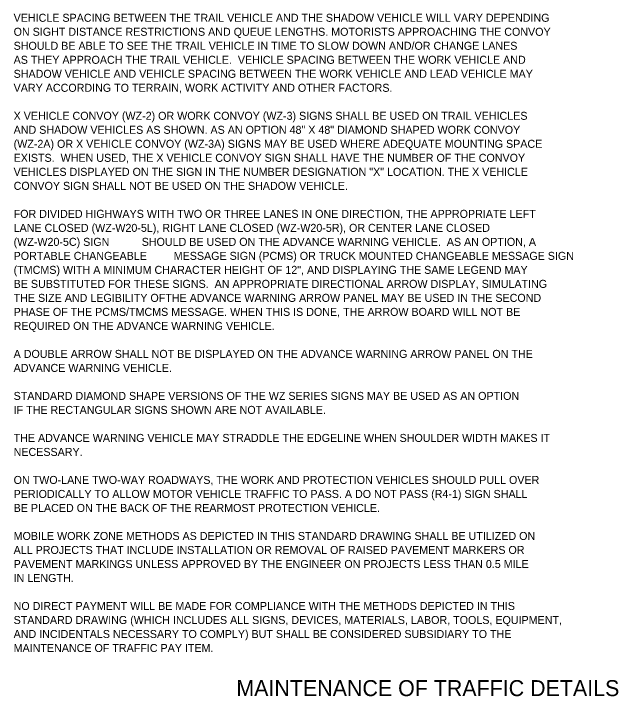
# Model space of a CAD drawing. Extents: x -747 to 834, y -5485 to -3577.
# Drawn here: x 360 to 813, y -5480 to -4968 of the extents above; entities that cross this region are included whole.
import ezdxf

# ---------------------------------------------------------------- set-up
doc = ezdxf.new("R2010")
doc.units = 0
doc.layers.add('R_Annotation', color=7, linetype='Continuous')
doc.layers.add('Working Level 1', color=7, linetype='Continuous')

msp = doc.modelspace()

# ---------------------------------------------------------------- texts
at = {"layer": 'R_Annotation'}
msp.add_text('MAINTENANCE OF TRAFFIC DETAILS', height=12, dxfattribs=at).set_placement((526.6, -5479.51))
at = {"layer": 'Working Level 1'}
for s, p in [('VEHICLE SPACING BETWEEN THE TRAIL VEHICLE AND THE SHADOW VEHICLE WILL VARY DEPENDING ', (359.65, -4973.93)), ('ON SIGHT DISTANCE RESTRICTIONS AND QUEUE LENGTHS. MOTORISTS APPROACHING THE CONVOY ', (359.65, -4984.43)), ('SHOULD BE ABLE TO SEE THE TRAIL VEHICLE IN TIME TO SLOW DOWN AND/OR CHANGE LANES ', (359.65, -4994.93)), ('AS THEY APPROACH THE TRAIL VEHICLE.  VEHICLE SPACING BETWEEN THE WORK VEHICLE AND ', (359.65, -5005.43)), ('SHADOW VEHICLE AND VEHICLE SPACING BETWEEN THE WORK VEHICLE AND LEAD VEHICLE MAY ', (359.65, -5015.93)), ('VARY ACCORDING TO TERRAIN, WORK ACTIVITY AND OTHER FACTORS.', (359.65, -5026.43)), ('X VEHICLE CONVOY (WZ-2) OR WORK CONVOY (WZ-3) SIGNS SHALL BE USED ON TRAIL VEHICLES', (359.65, -5047.43)), ('AND SHADOW VEHICLES AS SHOWN. AS AN OPTION 48" X 48" DIAMOND SHAPED WORK CONVOY', (359.65, -5057.93)), ('(WZ-2A) OR X VEHICLE CONVOY (WZ-3A) SIGNS MAY BE USED WHERE ADEQUATE MOUNTING SPACE', (359.65, -5068.43)), ('EXISTS.  WHEN USED, THE X VEHICLE CONVOY SIGN SHALL HAVE THE NUMBER OF THE CONVOY', (359.65, -5078.93)), ('VEHICLES DISPLAYED ON THE SIGN IN THE NUMBER DESIGNATION "X" LOCATION. THE X VEHICLE', (359.65, -5089.43)), ('CONVOY SIGN SHALL NOT BE USED ON THE SHADOW VEHICLE.', (359.65, -5099.93)), ('FOR DIVIDED HIGHWAYS WITH TWO OR THREE LANES IN ONE DIRECTION, THE APPROPRIATE LEFT ', (359.65, -5120.93)), ('LANE CLOSED (WZ-W20-5L), RIGHT LANE CLOSED (WZ-W20-5R), OR CENTER LANE CLOSED ', (359.65, -5131.43)), ('(WZ-W20-5C) SIGN', (359.65, -5141.93)), ('SHOULD BE USED ON THE ADVANCE WARNING VEHICLE.  AS AN OPTION, A ', (455.65, -5141.93)), ('PORTABLE CHANGEABLE', (359.65, -5152.43)), ('MESSAGE SIGN (PCMS) OR TRUCK MOUNTED CHANGEABLE MESSAGE SIGN ', (479.65, -5152.43)), ('(TMCMS) WITH A MINIMUM CHARACTER HEIGHT OF 12", AND DISPLAYING THE SAME LEGEND MAY ', (359.65, -5162.93)), ('BE SUBSTITUTED FOR THESE SIGNS.  AN APPROPRIATE DIRECTIONAL ARROW DISPLAY, SIMULATING ', (359.65, -5173.43)), ('THE SIZE AND LEGIBILITY OFTHE ADVANCE WARNING ARROW PANEL MAY BE USED IN THE SECOND ', (359.65, -5183.93)), ('PHASE OF THE PCMS/TMCMS MESSAGE. WHEN THIS IS DONE, THE ARROW BOARD WILL NOT BE ', (359.65, -5194.43)), ('REQUIRED ON THE ADVANCE WARNING VEHICLE.', (359.65, -5204.93)), ('A DOUBLE ARROW SHALL NOT BE DISPLAYED ON THE ADVANCE WARNING ARROW PANEL ON THE ', (359.65, -5225.93)), ('ADVANCE WARNING VEHICLE. ', (359.65, -5236.43)), ('STANDARD DIAMOND SHAPE VERSIONS OF THE WZ SERIES SIGNS MAY BE USED AS AN OPTION ', (359.65, -5257.43)), ('IF THE RECTANGULAR SIGNS SHOWN ARE NOT AVAILABLE.', (359.65, -5267.93)), ('THE ADVANCE WARNING VEHICLE MAY STRADDLE THE EDGELINE WHEN SHOULDER WIDTH MAKES IT ', (359.65, -5288.93)), ('NECESSARY.', (359.65, -5299.43)), ('ON TWO-LANE TWO-WAY ROADWAYS, THE WORK AND PROTECTION VEHICLES SHOULD PULL OVER', (359.65, -5320.43)), ('PERIODICALLY TO ALLOW MOTOR VEHICLE TRAFFIC TO PASS. A DO NOT PASS (R4-1) SIGN SHALL ', (359.65, -5330.93)), ('BE PLACED ON THE BACK OF THE REARMOST PROTECTION VEHICLE.', (359.65, -5341.43)), ('MOBILE WORK ZONE METHODS AS DEPICTED IN THIS STANDARD DRAWING SHALL BE UTILIZED ON ', (359.65, -5362.43)), ('ALL PROJECTS THAT INCLUDE INSTALLATION OR REMOVAL OF RAISED PAVEMENT MARKERS OR ', (359.65, -5372.93)), ('PAVEMENT MARKINGS UNLESS APPROVED BY THE ENGINEER ON PROJECTS LESS THAN 0.5 MILE ', (359.65, -5383.43)), ('IN LENGTH.', (359.65, -5393.93)), ('NO DIRECT PAYMENT WILL BE MADE FOR COMPLIANCE WITH THE METHODS DEPICTED IN THIS ', (359.65, -5414.93)), ('STANDARD DRAWING (WHICH INCLUDES ALL SIGNS, DEVICES, MATERIALS, LABOR, TOOLS, EQUIPMENT, ', (359.65, -5425.43)), ('AND INCIDENTALS NECESSARY TO COMPLY) BUT SHALL BE CONSIDERED SUBSIDIARY TO THE ', (359.65, -5435.93)), ('MAINTENANCE OF TRAFFIC PAY ITEM.', (359.65, -5446.43))]:
    msp.add_text(s, height=6, dxfattribs=at).set_placement(p)

doc.saveas('drawing.dxf')
